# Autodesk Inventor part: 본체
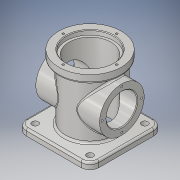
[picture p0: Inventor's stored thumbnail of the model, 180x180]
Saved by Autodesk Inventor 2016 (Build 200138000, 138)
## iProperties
Created: 2021-03
Part Number: 본체
Material: 알루미늄 6061
Document SubType Name: Modeling
Designer: WIN7
Density: 2.7 g/cm^3
Appearance: 알루미늄 - 평지
Mass: 830.909 g
Surface Area: 863.889 cm^2
Volume: 307.744 cm^3
Author: WIN7
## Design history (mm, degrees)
sketch "스케치1"
  geometry: C1 r 38 at (0, 0); 1 further point
  constraints: 1 centre point, 1 coincident
  dimensions: "d0" = 76 diameter of C1
extrude "돌출1" new body sketch "스케치1" distance "d1" = 54; taper "d2" = 0 deg
extrude "돌출2" join sketch "스케치1" distance "d3" = 57; taper "d4" = 0 deg
node "작업 평면1"
sketch "스케치2"
  geometry: C1 r 35 at (0, 0); 1 further point
  constraints: 1 centre point, 1 coincident
  dimensions: "d7" = 70 diameter of C1
extrude "돌출3" join sketch "스케치2" stored distance "d8" = 57; taper "d9" = 0 deg
sketch "스케치3"
  geometry: L1 (0, 0)-(0, 31)
  constraints: 2 end point, 1 vertical
  dimensions: "d10" = 31 distance of L1.start L1.end
hole "구멍1" sketch "스케치3" at (0, 31) diameter "d11" = 3.242; stored, may be unused: countersink angle "d15" = 90 deg, drill point angle "d17" = 118 deg; dims "d12" = 6, "d13" = 4, "d14" = 2, "d16" = 8
fillet "모깎기1" dims "d26" = 3
sketch "스케치6"
  geometry: 1 further point
hole "구멍2" sketch "스케치6" at (0, 0) diameter "d27" = 48; stored, may be unused: countersink angle "d31" = 90 deg, drill point angle "d33" = 118 deg; dims "d28" = 6, "d29" = 4, "d30" = 2, "d32" = 8
chamfer "모따기1" distance "d34" = 1; stored, may be unused: second distance "d35" = 2, angle "d36" = 45 deg
node "작업 평면3"
sketch "스케치7"
  geometry: C1 r 49 at (0, 0); 1 further point
  constraints: 1 centre point, 1 coincident
  dimensions: "d38" = 98 diameter of C1
extrude "돌출4" join sketch "스케치7" distance "d39" = 13; taper "d40" = 0 deg
node "작업 평면4"
sketch "스케치8"
  geometry: L1 (-57, -57)-(57, -57); L2 (57, -57)-(57, 57); L3 (57, 57)-(-57, 57); L4 (-57, 57)-(-57, -57); L5 (-57, -57)-(57, 57); L6 (57, -57)-(-57, 57); C1 r 33 at (0, 0) reference; 1 further point
  constraints: 12 end point, 2 midpoint, 2 parallel, 1 horizontal, 1 perpendicular
  dimensions: "d42" = 114 distance of L3.end L2.end; "d43" = 114 distance of L2.end L1.end
extrude "돌출5" join sketch "스케치8" distance "d44" = 10; taper "d45" = 0 deg
sketch "스케치9"
  geometry: 1 further point
hole "구멍3" sketch "스케치9" at (0, 0) diameter "d46" = 66; stored, may be unused: countersink angle "d50" = 90 deg, drill point angle "d52" = 118 deg; dims "d47" = 6, "d48" = 4, "d49" = 2, "d51" = 8
fillet "모깎기2" dims "d53" = 14
hole "구멍4" diameter "d56" = 10; stored, may be unused: countersink angle "d60" = 90 deg, drill point angle "d62" = 118 deg; dims "d54" = 10, "d55" = 10, "d57" = 6, "d58" = 4, "d59" = 2, "d61" = 8
hole "구멍5" diameter "d65" = 10; stored, may be unused: countersink angle "d69" = 90 deg, drill point angle "d71" = 118 deg; dims "d63" = 10, "d64" = 10, "d66" = 6, "d67" = 4, "d68" = 2, "d70" = 8
hole "구멍6" diameter "d74" = 10; stored, may be unused: countersink angle "d78" = 90 deg, drill point angle "d80" = 118 deg; dims "d72" = 10, "d73" = 10, "d75" = 6, "d76" = 4, "d77" = 2, "d79" = 8
hole "구멍7" diameter "d83" = 10; stored, may be unused: countersink angle "d87" = 90 deg, drill point angle "d89" = 118 deg; dims "d81" = 10, "d82" = 10, "d84" = 6, "d85" = 4, "d86" = 2, "d88" = 8
sketch "스케치10"
  geometry: C1 r 37 at (0, 0); 1 further point
  constraints: 1 centre point, 1 coincident
  dimensions: "d90" = 74 diameter of C1
extrude "돌출6" cut sketch "스케치10" distance "d91" = 7; taper "d92" = 0 deg
chamfer "모따기2" distance "d93" = 1; stored, may be unused: second distance "d94" = 2, angle "d95" = 45 deg
fillet "모깎기3" dims "d96" = 3
sketch "스케치11"
  geometry: L1 (0, 0)-(-42, 0); L2 (-42, -1.621)-(-42, 1.621) reference
  constraints: 2 end point, 1 midpoint
  dimensions: "d97" = 42 distance of L1.start L1.end (derived)
hole "구멍8" sketch "스케치11" at (-42, 0) diameter "d98" = 3.242; stored, may be unused: countersink angle "d102" = 90 deg, drill point angle "d104" = 118 deg; dims "d99" = 6, "d100" = 4, "d101" = 2, "d103" = 8
node "작업 평면5"
sketch "스케치12"
  geometry: L1 (79.8, 0)-(-79.8, 0) reference; L2 (0, -76.2)-(0, 79.2) reference; L3 (0, 23)-(0, -20); L4 (-7, 16)-(-7, -13); L5 (7, -13)-(7, 16); A1 r 7 centre (0, 16) between (7, 16) and (-7, 16); A2 r 7 centre (0, -13) between (-7, -13) and (7, -13); 2 further points
  constraints: 8 end point, 6 point on circle, 4 tangent, 2 centre point, 2 midpoint, 2 point on line, 1 parallel, 1 vertical
  dimensions: "d109" = 43 distance of L3.start L3.end; "d110" = 14 diameter of A2; "d111" = 20 distance from line of L1 L3.end
extrude "돌출7" join sketch "스케치12" stored distance "d112" = 7; taper "d113" = 0 deg
feature "면 기울기1" dims angle "d114" = 15 deg
fillet "모깎기4" dims "d115" = 3
fillet "모깎기5" dims "d116" = 3
fillet "모깎기6" dims "d117" = 3
hole "구멍9" diameter "d120" = 4.134; stored, may be unused: countersink angle "d124" = 90 deg, drill point angle "d126" = 118 deg; dims "d121" = 8, "d122" = 4, "d123" = 2, "d125" = 10, "d141" = 10, "d142" = 10
hole "구멍10" diameter "d129" = 4.134; stored, may be unused: countersink angle "d133" = 90 deg, drill point angle "d135" = 118 deg; dims "d130" = 8, "d131" = 4, "d132" = 2, "d134" = 10, "d143" = 10, "d144" = 10
node "작업 평면6"
sketch "스케치13"
  geometry: A1 r 50 centre (0, 0) between (0, -50) and (0, 50); 1 further point
  constraints: 2 point on circle, 1 centre point, 1 other
feature "엠보싱1" sketch "스케치13" dims "d139" = 0.5, "d140" = 0
node "솔리드1"
pattern_circular "원형 패턴1" dims angle "d19" = 360 deg
mirror "대칭1"
pattern_circular "원형 패턴2" dims angle "d106" = 360 deg
other parameters: "d37" = 0, "d41" = 0, "d108" = 55, "d136" = 3
